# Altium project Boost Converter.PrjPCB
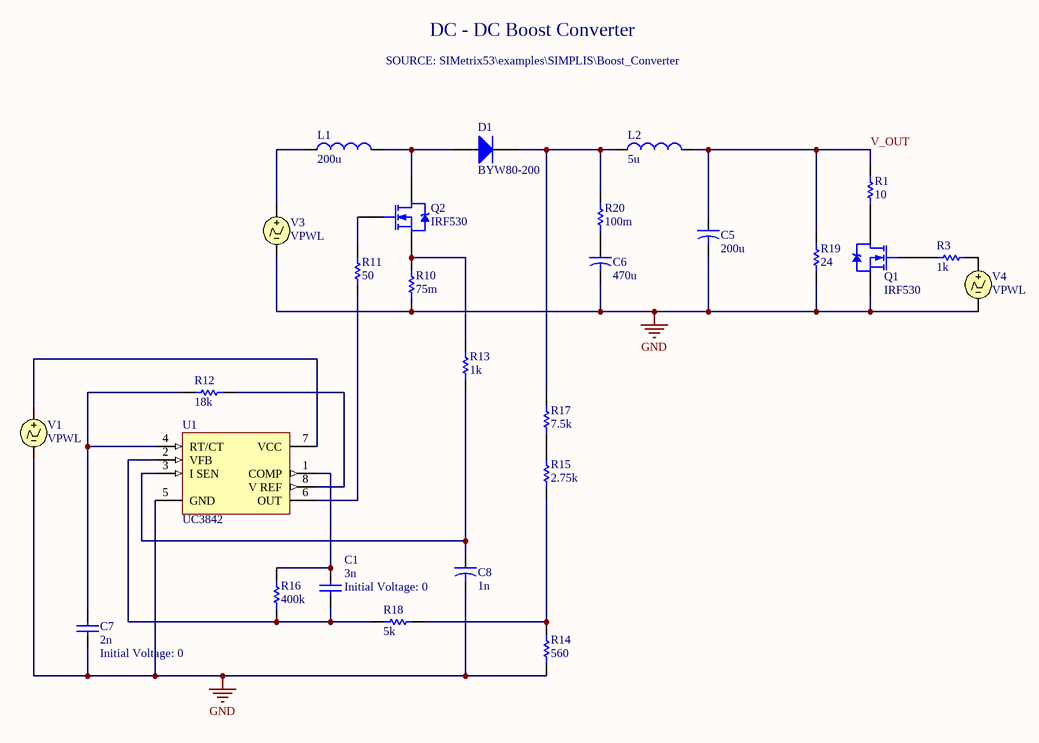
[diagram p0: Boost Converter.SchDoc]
1 sheet, 27 parts. Net scope: global (net labels, ports and power ports of the same name join across sheets).
Board file: Boost Converter.PcbDoc

## Sheet Boost Converter.SchDoc
size A4

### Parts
C1  value 3n  Initial Voltage: 0  [RAD-0.3]  (hidden comment: Cap)
C5  CC: 200u  [CAPR5-4X5]  (hidden comment: Cap Elec (L1-3))
C6  CC: 470u  [CAPR5-4X5]  (hidden comment: Cap Elec (L1-3))
C7  value 2n  Initial Voltage: 0  [RAD-0.3]  (hidden comment: Cap)
C8  CC: 1n  [CAPR5-4X5]  (hidden comment: Cap Elec (L1-3))
D1  BYW80-200  [SMC]
L1  value 200u  [0402-A]  (hidden comment: Lossy Inductor)
L2  value 5u  [0402-A]  (hidden comment: Lossy Inductor)
Q1  IRF530  [TO-220AB]
Q2  IRF530  [TO-220AB]
R1  value 10  [AXIAL-0.3]  (hidden comment: Res1)
R3  value 1k  [AXIAL-0.3]  (hidden comment: Res1)
R10  value 75m  [AXIAL-0.3]  (hidden comment: Res1)
R11  value 50  [AXIAL-0.3]  (hidden comment: Res1)
R12  value 18k  [AXIAL-0.3]  (hidden comment: Res1)
R13  value 1k  [AXIAL-0.3]  (hidden comment: Res1)
R14  value 560  [AXIAL-0.3]  (hidden comment: Res1)
R15  value 2.75k  [AXIAL-0.3]  (hidden comment: Res1)
R16  value 400k  [AXIAL-0.3]  (hidden comment: Res1)
R17  value 7.5k  [AXIAL-0.3]  (hidden comment: Res1)
R18  value 5k  [AXIAL-0.3]  (hidden comment: Res1)
R19  value 24  [AXIAL-0.3]  (hidden comment: Res1)
R20  value 100m  [AXIAL-0.3]  (hidden comment: Res1)
U1  UC3842  [SO8_L]
V1  VPWL  [HDR1X2H]
V3  VPWL  [HDR1X2H]
V4  VPWL  [HDR1X2H]

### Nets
GND: C5.2 C6.2 C7.2 C8.2 Q1.3(S) R10.1 R14.1 R19.2 U1.5(GND) V1.2 V3.2 V4.2
V_OUT: C5.1 L2.2 R1.1 R19.1
NetC1_1: C1.1 R16.2 U1.1(COMP)
NetC1_2: C1.2 R16.1 R18.2 U1.2(VFB)
NetC6_1: C6.1 R20.1
NetC7_1: C7.1 R12.2 U1.4(RT/CT)
NetC8_1: C8.1 R13.1 U1.3(I_SEN)
NetD1_1: D1.1(A) L1.2 Q2.2(D)
NetD1_2: D1.2(K) L2.1 R17.2 R20.2
NetL1_1: L1.1 V3.1
NetQ1_1: Q1.1(G) R3.1
NetQ1_2: Q1.2(D) R1.2
NetQ2_1: Q2.1(G) R11.2
NetQ2_3: Q2.3(S) R10.2 R13.2
NetR3_2: R3.2 V4.1
NetR11_1: R11.1 U1.6(OUT)
NetR12_1: R12.1 U1.8(V_REF)
NetR14_2: R14.2 R15.1 R18.1
NetR15_2: R15.2 R17.1
NetU1_7: U1.7(VCC) V1.1

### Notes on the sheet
- DC - DC Boost Converter
- SOURCE: SIMetrix53\examples\SIMPLIS\Boost_Converter

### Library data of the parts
C1 C7 = Cap: Capacitor
C5 = Cap Elec (L1-3): Electrolytic Capacitor (Levels 1-3); RSH_CC: 100Meg; RESR: 20m; LEVEL: 2
C6 = Cap Elec (L1-3): Electrolytic Capacitor (Levels 1-3); LEVEL: 2; RSH_CC: 100Meg; RESR: 30m
C8 = Cap Elec (L1-3): Electrolytic Capacitor (Levels 1-3); RSH_CC: 1G; RESR: 50; LEVEL: 2
D1 = BYW80-200: High-Efficiency Fast Recovery Rectifier Diode
L1 L2 = Inductor (Lossy): Code_IEC: 1005; RSERIES: 10m; RSHUNT: 1G
Q1 Q2 = IRF530: HEXFET N-Channel Power MOSFET; Note: Pin 2 is electrically connected to pin 4.
R1 R3 R10-R20 = Res1: Resistor
U1 = UC3842: High-Performance Current Mode PWM Controller
V1 V3 V4 = VPWL: Piecewise Linear Voltage Source; Note: PCB Footprint - Not required; Sim Note: To add model file containing time-current pairs of values, enter model location under "General Tab" in "Full Path" box.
